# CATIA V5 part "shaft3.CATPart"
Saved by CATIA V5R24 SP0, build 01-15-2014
Part number: shaft3
Bounding box of the stored display mesh (mm): x -12 to 12, y -11.856 to 11.856, z -8 to 100
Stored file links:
  G:\내 드라이브\04_WORK\00_LECTURE\CAD2020\exam\shaft3.CATPart
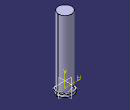
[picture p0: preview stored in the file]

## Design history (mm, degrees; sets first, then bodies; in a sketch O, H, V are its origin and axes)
Body1 (main body)
  Sketch1 on xy-plane, origin (0, 0, 0), H (1, 0, 0), V (0, 1, 0)
    circle A1 centre (0, 0) radius 10
    radius A1 = 10
  Pad1: profile Sketch1, direction (0, 0, 1), length 100
  Sketch2 on xy-plane, origin (0, 0, 0), H (1, 0, 0), V (0, 1, 0)
    circle A1 centre (0, 0) radius 12
    radius A1 = 12
  Pad2: profile Sketch2, direction (0, 0, -1), length 4
  Sketch3 on yz-plane, origin (0, 0, 0), H (0, 1, 0), V (0, 0, 1)
    arc A1 centre (0, 12) radius 20 from (0, -8) to (12, -4) ccw
    point P1 (0, 12)
    axis line L1 (0, 20.8302) -> (0, -12.4363)
    point P6 (0, 20.8302)
    point P8 (0, -8)
    line L2 (0, -8) -> (0, -4)
    line L3 (0, -4) -> (12, -4)
    radius A1 = 20
    coincidence: P1 V, P6 V, L1 P8
    vertical: L1 V, L2 V
    horizontal: L3 H
  Shaft1: profile Sketch3, axis Sketch3.L1, angle 360
  Sketch4 on zx-plane, origin (0, 0, 0), H (-1, 0, 0), V (0, 0, 1)
    projected arc E1 centre (0, 12.0004) radius 20.0004 from (-12, -4) to (12, -4) ccw from face of Shaft1 from Sketch3.A1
